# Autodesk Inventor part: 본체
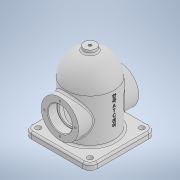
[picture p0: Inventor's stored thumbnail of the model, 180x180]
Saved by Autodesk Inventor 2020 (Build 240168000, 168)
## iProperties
Created: 2021-07
Part Number: 본체
Material: 일반
Document SubType Name: Modeling
Designer: Owner
Density: 1 g/cm^3
Appearance: 기본값
Mass: 320.734 g
Surface Area: 800.675 cm^2
Volume: 320.734 cm^3
Author: Owner
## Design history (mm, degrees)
sketch "스케치1"
  geometry: C1 r 40 at (0, 0); 1 further point
  constraints: 1 centre point, 1 coincident
  dimensions: "d0" = 80 diameter of C1
extrude "돌출1" new body sketch "스케치1" distance "d1" = 124; taper "d2" = 0 deg
fillet "모깎기1" dims "d3" = 40
feature "쉘1" dims "d4" = 8
sketch "스케치2"
  geometry: L1 (-55, -55)-(55, -55); L2 (55, -55)-(55, 55); L3 (55, 55)-(-55, 55); L4 (-55, 55)-(-55, -55); L5 (-55, -55)-(55, 55); L6 (55, -55)-(-55, 55); C1 r 40 at (0, 0) reference; C2 r 32 at (0, 0) reference; C3 r 32 at (0, 0) reference; C4 r 40 at (0, 0) reference; 1 further point
  constraints: 12 end point, 2 midpoint, 2 parallel, 1 horizontal, 1 perpendicular
  dimensions: "d5" = 110 distance of L3.end L2.end; "d6" = 110 distance of L2.end L1.end
extrude "돌출2" join sketch "스케치2" distance "d7" = 10; taper "d8" = 0 deg
node "작업 평면4"
sketch "스케치4"
  geometry: L1 (55, 0)-(-55, 0) reference; C1 r 31 at (0, 48); 1 further point
  constraints: 1 centre point
  dimensions: "d15" = 62 diameter of C1; "d16" = 48 distance from line of C1.centre L1
extrude "돌출4" join sketch "스케치4" stored distance "d17" = 124; taper "d18" = 0 deg
sketch "스케치5"
  geometry: C1 r 31 at (0, 0) reference; 2 further points
  constraints: 1 coincident
hole "구멍1" sketch "스케치5" at (0, 0) diameter "d19" = 33; stored, may be unused: countersink angle "d23" = 90 deg, drill point angle "d25" = 0 deg; dims "d20" = 9, "d21" = 40, "d22" = 15, "d24" = 11
sketch "스케치6"
  geometry: C1 r 20 at (0, 0) reference; C2 r 31 at (0, 0) reference; 2 further points
  dimensions: "d26" = 25.5 distance of point (0, 25.5) C1.centre
hole "구멍2" sketch "스케치6" at (0, 25.5) diameter "d27" = 3.242; stored, may be unused: countersink angle "d31" = 90 deg, drill point angle "d33" = 118 deg; dims "d28" = 8, "d29" = 40, "d30" = 15, "d32" = 10
fillet "모깎기2" dims "d37" = 3
chamfer "모따기1" distance "d38" = 1; stored, may be unused: second distance "d39" = 2, angle "d40" = 45 deg
fillet "모깎기3" dims "d41" = 0.3
node "작업 평면5"
sketch "스케치7"
  geometry: C1 r 10 at (0, 0); 1 further point
  constraints: 1 centre point, 1 coincident
  dimensions: "d43" = 20 diameter of C1
extrude "돌출5" join sketch "스케치7" stored distance "d44" = 124; taper "d45" = 0 deg
sketch "스케치8"
  geometry: C1 r 10 at (0, 0) reference; 2 further points
  constraints: 1 coincident
hole "구멍3" sketch "스케치8" at (0, 0) diameter "d46" = 4.917; stored, may be unused: countersink angle "d50" = 90 deg, drill point angle "d52" = 118 deg; dims "d47" = 12, "d48" = 40, "d49" = 15, "d51" = 17.1
fillet "모깎기4" dims "d53" = 3
fillet "모깎기5" dims "d54" = 3
fillet "모깎기6" dims "d55" = 12
sketch "스케치10"
  geometry: A1 r 12 centre (-43, -43) between (-55, -43) and (-43, -55) reference; 2 further points
  constraints: 1 coincident
hole "구멍4" sketch "스케치10" at (-43, -43) diameter "d56" = 9; stored, may be unused: countersink angle "d60" = 90 deg, drill point angle "d62" = 118 deg; dims "d57" = 12, "d58" = 40, "d59" = 15, "d61" = 17.1
node "작업 평면6"
sketch "스케치11"
  geometry: L1 (0, -43)-(0, 43) reference; 3 further points
  constraints: 1 horizontal alignment, 1 midpoint, 1 other
feature "엠보싱1" sketch "스케치11" dims "d1" = 124, "d2" = 0, "d7" = 10, "d8" = 0, "d66" = 0.5, "d67" = 0
fillet "모깎기7" dims "d68" = 3
node "솔리드1"
pattern_circular "원형 패턴1" dims angle "d35" = 360 deg
mirror "미러1"
pattern_circular "원형 패턴2" dims angle "d64" = 360 deg
node "투영된 루프1"
node "투영된 루프2"
feature "A9D066F2-1C7D-4E18-AEED-F7BC21143FA4" dims "d19" = 33, "d20" = 9, "d21" = 40, "d22" = 15, "d23" = 90 deg, "d24" = 11, "d25" = 0
other parameters: "d42" = -129
